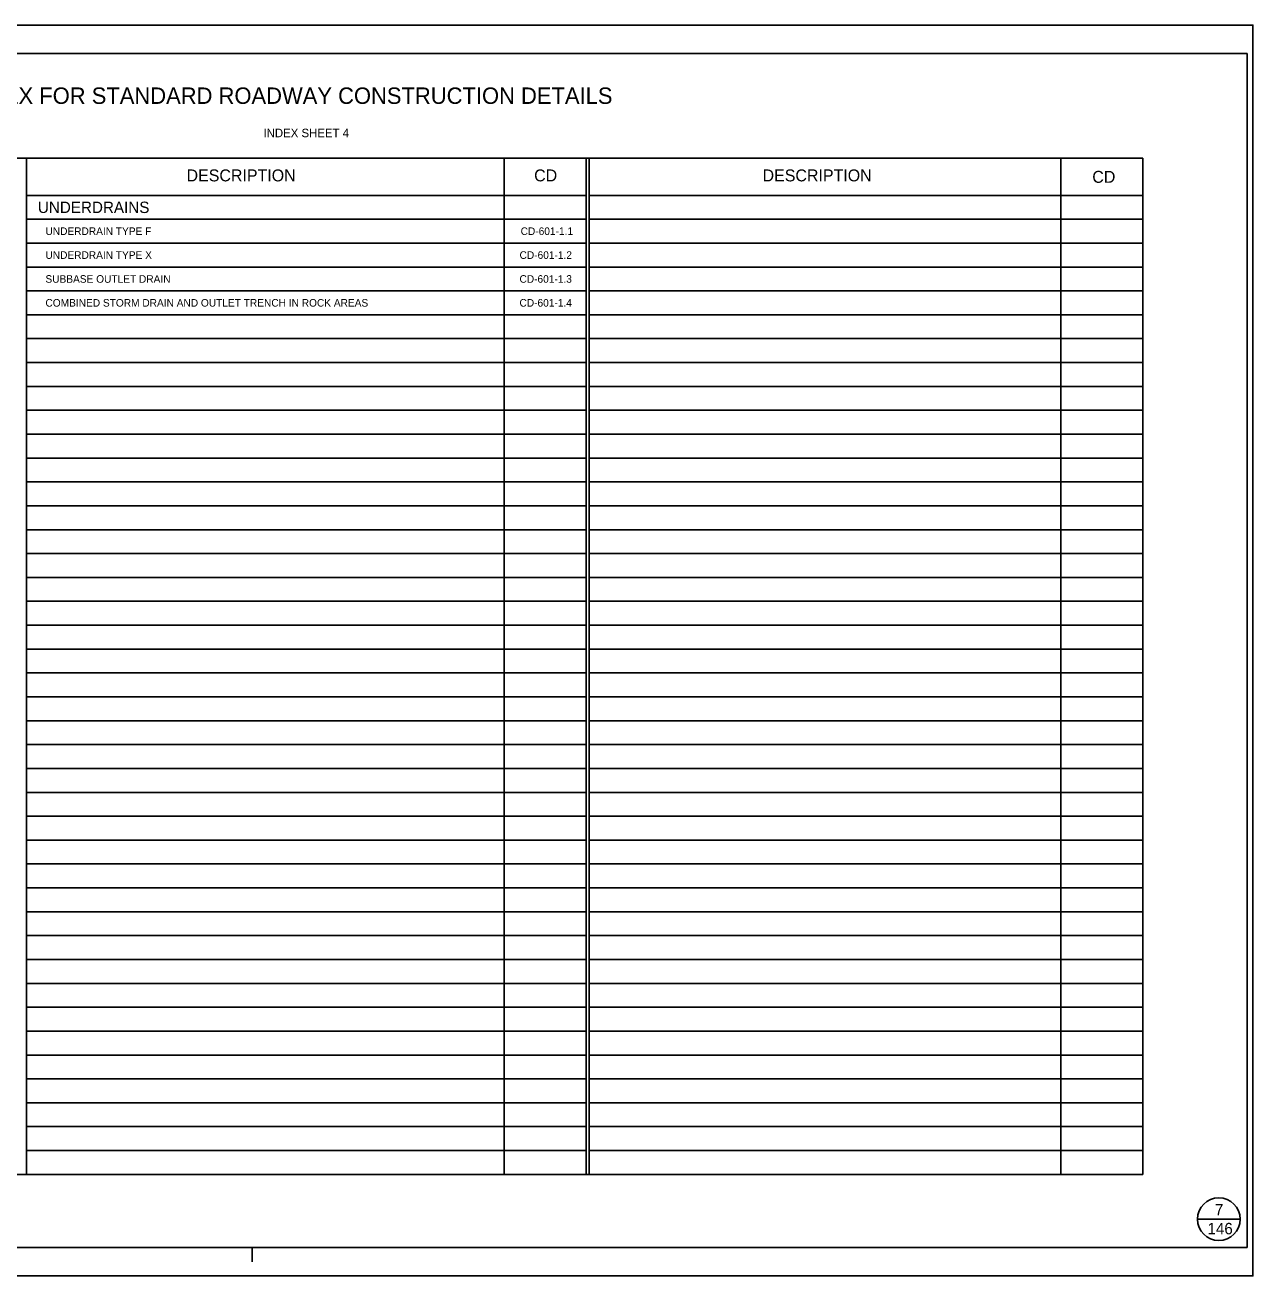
# Model space of a CAD drawing. Extents: x 503613 to 504661, y 499104 to 499764.
# Drawn here: x 504013 to 504661, y 499104 to 499764 of the extents above; entities that cross this region are included whole.
import ezdxf

# ---------------------------------------------------------------- set-up
doc = ezdxf.new("R2010")
doc.units = 0
for name, color, linetype in [('1', 7, 'Continuous'), ('39', 7, 'Continuous'), ('41', 7, 'Continuous')]:
    doc.layers.add(name, color=color, linetype=linetype)

msp = doc.modelspace()

# ---------------------------------------------------------------- linework, layer by layer
at = {"layer": '1'}
for p, q in [((504661.22, 499764.48), (503613.04, 499764.48)), ((504658.22, 499749.48), (503668.22, 499749.48)), ((504658.22, 499119.48), (504658.22, 499749.48)), ((503717.27, 499694.28), (504603.1, 499694.28)), ((504014.12, 499158.06), (504014.12, 499694.28)), ((504014.12, 499674.59), (504014.12, 499694.28)), ((504266.09, 499158.06), (504266.09, 499694.28)), ((504266.09, 499674.59), (504266.09, 499694.28)), ((504309.4, 499158.06), (504309.4, 499694.28)), ((504309.4, 499674.59), (504309.4, 499694.28)), ((504310.97, 499158.06), (504310.97, 499694.28)), ((504310.97, 499674.59), (504310.97, 499694.28)), ((504559.79, 499158.06), (504559.79, 499694.28)), ((504559.79, 499674.59), (504559.79, 499694.28)), ((504603.1, 499158.06), (504603.1, 499694.28)), ((504603.1, 499674.59), (504603.1, 499694.28)), ((504014.12, 499674.59), (504309.4, 499674.59)), ((504310.97, 499674.59), (504603.1, 499674.59)), ((504335.38, 499674.59), (504603.1, 499674.59)), ((504014.12, 499662), (504309.4, 499662)), ((504310.97, 499662), (504603.1, 499662)), ((504014.12, 499649.4), (504309.4, 499649.4)), ((504310.97, 499649.4), (504603.1, 499649.4)), ((504014.12, 499636.8), (504309.4, 499636.8)), ((504310.97, 499636.8), (504603.1, 499636.8)), ((504014.12, 499624.2), (504309.4, 499624.2)), ((504310.97, 499624.2), (504603.1, 499624.2)), ((504014.12, 499611.6), (504309.4, 499611.6)), ((504310.97, 499611.6), (504603.1, 499611.6)), ((504014.12, 499599), (504309.4, 499599)), ((504310.97, 499599), (504603.1, 499599)), ((504014.12, 499586.41), (504309.4, 499586.41)), ((504310.97, 499586.41), (504603.1, 499586.41)), ((504014.12, 499573.81), (504309.4, 499573.81)), ((504310.97, 499573.81), (504603.1, 499573.81)), ((504014.12, 499561.21), (504309.4, 499561.21)), ((504310.97, 499561.21), (504603.1, 499561.21)), ((504014.12, 499548.61), (504309.4, 499548.61)), ((504310.97, 499548.61), (504603.1, 499548.61)), ((504014.12, 499536.01), (504309.4, 499536.01)), ((504310.97, 499536.01), (504603.1, 499536.01)), ((504014.12, 499523.41), (504309.4, 499523.41)), ((504310.97, 499523.41), (504603.1, 499523.41)), ((504014.12, 499510.82), (504309.4, 499510.82)), ((504310.97, 499510.82), (504603.1, 499510.82)), ((504014.12, 499498.22), (504309.4, 499498.22)), ((504310.97, 499498.22), (504603.1, 499498.22)), ((504014.12, 499485.62), (504309.4, 499485.62)), ((504310.97, 499485.62), (504603.1, 499485.62)), ((504014.12, 499473.02), (504309.4, 499473.02)), ((504310.97, 499473.02), (504603.1, 499473.02)), ((504014.12, 499460.42), (504309.4, 499460.42)), ((504310.97, 499460.42), (504603.1, 499460.42)), ((504014.12, 499447.82), (504309.4, 499447.82)), ((504310.97, 499447.82), (504603.1, 499447.82)), ((504014.12, 499435.22), (504309.4, 499435.22)), ((504310.97, 499435.22), (504603.1, 499435.22)), ((504014.12, 499422.63), (504309.4, 499422.63)), ((504310.97, 499422.63), (504603.1, 499422.63)), ((504014.12, 499410.03), (504309.4, 499410.03)), ((504310.97, 499410.03), (504603.1, 499410.03)), ((504014.12, 499397.43), (504309.4, 499397.43)), ((504310.97, 499397.43), (504603.1, 499397.43)), ((504014.12, 499384.83), (504309.4, 499384.83)), ((504310.97, 499384.83), (504603.1, 499384.83)), ((504014.12, 499372.23), (504309.4, 499372.23)), ((504310.97, 499372.23), (504603.1, 499372.23)), ((504014.12, 499359.63), (504309.4, 499359.63)), ((504310.97, 499359.63), (504603.1, 499359.63)), ((504014.12, 499347.04), (504309.4, 499347.04)), ((504310.97, 499347.04), (504603.1, 499347.04)), ((504014.12, 499334.44), (504309.4, 499334.44)), ((504310.97, 499334.44), (504603.1, 499334.44)), ((504014.12, 499321.84), (504309.4, 499321.84)), ((504310.97, 499321.84), (504603.1, 499321.84)), ((504014.12, 499309.24), (504309.4, 499309.24)), ((504310.97, 499309.24), (504603.1, 499309.24)), ((504014.12, 499296.64), (504309.4, 499296.64)), ((504310.97, 499296.64), (504603.1, 499296.64)), ((504014.12, 499284.04), (504309.4, 499284.04)), ((504310.97, 499284.04), (504603.1, 499284.04)), ((504014.12, 499271.44), (504309.4, 499271.44)), ((504310.97, 499271.44), (504603.1, 499271.44)), ((504014.12, 499258.85), (504309.4, 499258.85)), ((504310.97, 499258.85), (504603.1, 499258.85)), ((504014.12, 499246.25), (504309.4, 499246.25)), ((504310.97, 499246.25), (504603.1, 499246.25)), ((504014.12, 499233.65), (504309.4, 499233.65)), ((504310.97, 499233.65), (504603.1, 499233.65)), ((504014.12, 499221.05), (504309.4, 499221.05)), ((504310.97, 499221.05), (504603.1, 499221.05)), ((504014.12, 499208.45), (504309.4, 499208.45)), ((504310.97, 499208.45), (504603.1, 499208.45)), ((504014.12, 499195.85), (504309.4, 499195.85)), ((504310.97, 499195.85), (504603.1, 499195.85)), ((504014.12, 499183.26), (504309.4, 499183.26)), ((504310.97, 499183.26), (504603.1, 499183.26)), ((504014.12, 499170.66), (504309.4, 499170.66)), ((504310.97, 499170.66), (504603.1, 499170.66)), ((503717.27, 499158.06), (504603.1, 499158.06)), ((504643.22, 499134.48), (504631.97, 499134.48)), ((504643.22, 499134.48), (504654.47, 499134.48)), ((503668.22, 499119.48), (504658.22, 499119.48)), ((504133.22, 499111.98), (504133.22, 499119.48)), ((504661.22, 499104.48), (503613.04, 499104.48))]:
    msp.add_line(p, q, dxfattribs=at)
msp.add_circle((504643.22, 499134.48), 11.25, dxfattribs=at)
at = {"layer": '41'}
msp.add_lwpolyline([(503613.04, 499764.48), (504661.22, 499764.48), (504661.22, 499104.48), (503613.04, 499104.48)], close=True, dxfattribs=at)

# ---------------------------------------------------------------- texts
at = {"layer": '1'}
for p in [(504098.57, 499681.98), (504402.48, 499681.98)]:
    msp.add_text('DESCRIPTION', height=6.2992, dxfattribs=at).set_placement(p)
at = {"layer": '39'}
for s, height, p in [('INDEX FOR STANDARD ROADWAY CONSTRUCTION DETAILS', 8.6614, (503982.24, 499722.87)), ('INDEX SHEET 4', 4.5, (504139.14, 499705.27)), ('CD', 6.299, (504281.95, 499681.98)), ('CD', 6.299, (504576.44, 499681.22)), ('UNDERDRAINS', 6, (504020.12, 499665.29)), ('UNDERDRAIN TYPE F', 4, (504024.12, 499653.7)), ('CD-601-1.1', 4, (504274.83, 499653.7)), ('UNDERDRAIN TYPE X', 4, (504024.12, 499641.1)), ('CD-601-1.2', 4, (504274.26, 499641.1)), ('SUBBASE OUTLET DRAIN ', 4, (504024.12, 499628.5)), ('CD-601-1.3', 4, (504274.22, 499628.5)), ('COMBINED STORM DRAIN AND OUTLET TRENCH IN ROCK AREAS', 4, (504024.12, 499615.9)), ('CD-601-1.4', 4, (504274.22, 499615.9)), ('7', 6, (504641.15, 499136.48)), ('146', 6, (504637.19, 499126.48))]:
    msp.add_text(s, height=height, dxfattribs=at).set_placement(p)

doc.saveas('drawing.dxf')
